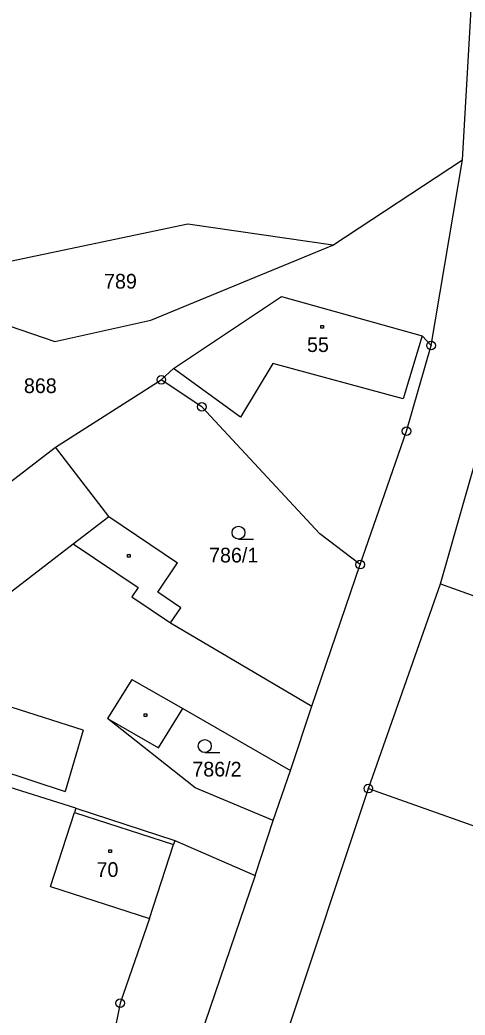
# Model space of a CAD drawing. Extents: x -791032 to -787751, y -1106872 to -1104403.
# Drawn here: x -789588.6 to -789537.2, y -1105935.3 to -1105820.2 of the extents above; entities that cross this region are included whole.
import ezdxf

# ---------------------------------------------------------------- set-up
doc = ezdxf.new("R2010")
doc.units = 0
for name, color, linetype in [('Vrstva 1', 7, 'Continuous'), ('Vrstva 14', 7, 'Continuous'), ('Vrstva 15', 7, 'Continuous'), ('Vrstva 2', 7, 'Continuous'), ('Vrstva 23', 7, 'Continuous'), ('Vrstva 25', 7, 'Continuous'), ('Vrstva 28', 7, 'Continuous')]:
    doc.layers.add(name, color=color, linetype=linetype)

msp = doc.modelspace()

# ---------------------------------------------------------------- linework, layer by layer
at = {"layer": 'Vrstva 1'}
for p, q in [((-789537.47, -1105836.39), (-789534.82, -1105789.69)), ((-789552.46, -1105846.24), (-789537.47, -1105836.39)), ((-789541.1, -1105857.87), (-789537.47, -1105836.39)), ((-789569.23, -1105843.82), (-789603.21, -1105850.97)), ((-789552.46, -1105846.24), (-789569.23, -1105843.82)), ((-789573.49, -1105854.92), (-789552.46, -1105846.24)), ((-789603.21, -1105850.97), (-789584.6, -1105857.41)), ((-789570.89, -1105860.53), (-789558.38, -1105852.18)), ((-789558.38, -1105852.18), (-789542.12, -1105856.75)), ((-789584.6, -1105857.41), (-789573.49, -1105854.92)), ((-789541.1, -1105857.87), (-789542.12, -1105856.75)), ((-789543.95, -1105867.77), (-789541.1, -1105857.87)), ((-789572.28, -1105861.83), (-789570.89, -1105860.53)), ((-789584.52, -1105869.63), (-789572.28, -1105861.83)), ((-789567.6, -1105864.96), (-789572.28, -1105861.83)), ((-789553.94, -1105879.63), (-789567.6, -1105864.96)), ((-789540.01, -1105885.41), (-789534.63, -1105866.51)), ((-789549.29, -1105883.2), (-789543.95, -1105867.77)), ((-789602.89, -1105883.75), (-789584.52, -1105869.63)), ((-789578.36, -1105877.64), (-789584.52, -1105869.63)), ((-789578.36, -1105877.64), (-789570.4, -1105883)), ((-789549.29, -1105883.2), (-789553.94, -1105879.63)), ((-789572.69, -1105886.4), (-789570.4, -1105883)), ((-789554.9, -1105899.56), (-789549.29, -1105883.2)), ((-789548.35, -1105909.1), (-789540.01, -1105885.41)), ((-789540.01, -1105885.41), (-789528.56, -1105889.56)), ((-789570.03, -1105888.18), (-789572.69, -1105886.4)), ((-789571.21, -1105889.93), (-789570.03, -1105888.18)), ((-789571.21, -1105889.93), (-789554.9, -1105899.56)), ((-789572.61, -1105904.38), (-789569.8, -1105899.85)), ((-789569.8, -1105899.85), (-789557.35, -1105907.01)), ((-789557.35, -1105907.01), (-789554.9, -1105899.56)), ((-789568.35, -1105908.99), (-789578.51, -1105900.99)), ((-789578.51, -1105900.99), (-789572.61, -1105904.38)), ((-789582.15, -1105911.37), (-789596.86, -1105906.75)), ((-789559.34, -1105912.78), (-789557.35, -1105907.01)), ((-789578.49, -1105999.72), (-789548.35, -1105909.1)), ((-789559.34, -1105912.78), (-789568.35, -1105908.99)), ((-789548.35, -1105909.1), (-789499.87, -1105926.23)), ((-789582.15, -1105911.37), (-789582.3, -1105911.85)), ((-789582.15, -1105911.37), (-789570.73, -1105915.08)), ((-789585.08, -1105920.41), (-789582.3, -1105911.85)), ((-789561.42, -1105919.14), (-789559.34, -1105912.78)), ((-789573.66, -1105924.11), (-789570.89, -1105915.55)), ((-789570.73, -1105915.08), (-789570.89, -1105915.55)), ((-789570.73, -1105915.08), (-789561.42, -1105919.14)), ((-789561.42, -1105919.14), (-789571.94, -1105949.95)), ((-789585.08, -1105920.41), (-789573.66, -1105924.11)), ((-789573.66, -1105924.11), (-789577.05, -1105933.91)), ((-789577.05, -1105933.91), (-789582.63, -1105962.19))]:
    msp.add_line(p, q, dxfattribs=at)
at = {"layer": 'Vrstva 2'}
for p, q in [((-789542.12, -1105856.75), (-789544.31, -1105864.04)), ((-789563.13, -1105866.15), (-789570.89, -1105860.53)), ((-789559.4, -1105859.93), (-789563.13, -1105866.15)), ((-789544.31, -1105864.04), (-789559.4, -1105859.93)), ((-789582.46, -1105880.79), (-789578.36, -1105877.64)), ((-789596.73, -1105891.76), (-789582.46, -1105880.79)), ((-789582.46, -1105880.79), (-789574.96, -1105885.83)), ((-789574.96, -1105885.83), (-789575.69, -1105886.91)), ((-789575.69, -1105886.91), (-789571.21, -1105889.93)), ((-789575.69, -1105896.47), (-789578.51, -1105900.99)), ((-789575.69, -1105896.47), (-789569.8, -1105899.85)), ((-789581.32, -1105902.33), (-789589.52, -1105899.73)), ((-789581.32, -1105902.33), (-789583.41, -1105909.42)), ((-789596.32, -1105905.19), (-789583.41, -1105909.42)), ((-789582.3, -1105911.85), (-789570.89, -1105915.55))]:
    msp.add_line(p, q, dxfattribs=at)
at = {"layer": 'Vrstva 23'}
for p, q in [((-789563.36, -1105880.25), (-789561.61, -1105880.25)), ((-789567.26, -1105904.93), (-789565.51, -1105904.93))]:
    msp.add_line(p, q, dxfattribs=at)
for centre in [(-789563.36, -1105879.5), (-789567.26, -1105904.18)]:
    msp.add_circle(centre, 0.75, dxfattribs=at)
at = {"layer": 'Vrstva 25'}
for p, q in [((-789553.85, -1105855.56), (-789553.55, -1105855.56)), ((-789553.85, -1105855.86), (-789553.85, -1105855.56)), ((-789553.55, -1105855.86), (-789553.85, -1105855.86)), ((-789553.55, -1105855.56), (-789553.55, -1105855.86)), ((-789576.2, -1105882.04), (-789575.9, -1105882.04)), ((-789576.2, -1105882.34), (-789576.2, -1105882.04)), ((-789575.9, -1105882.34), (-789576.2, -1105882.34)), ((-789575.9, -1105882.04), (-789575.9, -1105882.34)), ((-789574.26, -1105900.46), (-789573.96, -1105900.46)), ((-789574.26, -1105900.76), (-789574.26, -1105900.46)), ((-789573.96, -1105900.76), (-789574.26, -1105900.76)), ((-789573.96, -1105900.46), (-789573.96, -1105900.76)), ((-789578.33, -1105916.19), (-789578.03, -1105916.19)), ((-789578.33, -1105916.49), (-789578.33, -1105916.19)), ((-789578.03, -1105916.49), (-789578.33, -1105916.49)), ((-789578.03, -1105916.19), (-789578.03, -1105916.49))]:
    msp.add_line(p, q, dxfattribs=at)
at = {"layer": 'Vrstva 28'}
for centre, radius in [((-789541.1, -1105857.87), 0.5), ((-789541.1, -1105857.87), 0.01), ((-789572.28, -1105861.83), 0.5), ((-789572.28, -1105861.83), 0.01), ((-789567.6, -1105864.96), 0.5), ((-789567.6, -1105864.96), 0.01), ((-789543.95, -1105867.77), 0.5), ((-789543.95, -1105867.77), 0.01), ((-789549.29, -1105883.2), 0.5), ((-789549.29, -1105883.2), 0.01), ((-789548.35, -1105909.1), 0.5), ((-789548.35, -1105909.1), 0.01), ((-789577.05, -1105933.91), 0.5), ((-789577.05, -1105933.91), 0.01)]:
    msp.add_circle(centre, radius, dxfattribs=at)

# ---------------------------------------------------------------- texts
at = {"layer": 'Vrstva 14'}
for s, p in [('789', (-789578.903, -1105851.28)), ('868', (-789588.166, -1105863.36)), ('786/1', (-789566.76, -1105882.95)), ('786/2', (-789568.696, -1105907.7))]:
    msp.add_text(s, height=1.7, dxfattribs=at).set_placement(p)
at = {"layer": 'Vrstva 15'}
for s, p in [('55', (-789555.439, -1105858.61)), ('70', (-789579.773, -1105919.31))]:
    msp.add_text(s, height=1.7, dxfattribs=at).set_placement(p)

doc.saveas('drawing.dxf')
